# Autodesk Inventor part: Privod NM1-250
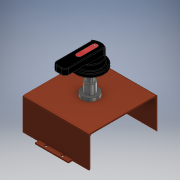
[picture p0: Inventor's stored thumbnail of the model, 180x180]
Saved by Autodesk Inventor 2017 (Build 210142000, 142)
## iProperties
Part Number: Privod NM1-250
Material: Типовые
Document SubType Name: Modeling
Designer: RSagdiev
Density: 1 g/cm^3
Appearance: По умолчанию
Author: RSagdiev
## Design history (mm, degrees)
sketch "Эскиз1"
  geometry: L1 (-26.25, 60.5)-(26.25, 60.5); L2 (26.25, 60.5)-(26.25, 52); L3 (26.25, 52)-(15.125, 52); L4 (-26.25, 52)-(-26.25, 60.5); L5 (0, 0)-(119.698, 0); L6 (0, 0)-(-104.809, 0); L7 (0, 94.88)-(0, -60.954); L8 (-15.125, 52)-(-11.125, 52); L9 (-11.125, 52)-(-11.125, 57); L10 (-13.125, 59)-(-13.125, 59); L11 (-15.125, 57)-(-15.125, 52); L12 (11.125, 52)-(11.125, 57); L13 (13.125, 59)-(13.125, 59); L14 (15.125, 52)-(11.125, 52); L15 (15.125, 57)-(15.125, 52); L16 (-15.125, 52)-(-26.25, 52); L17 (-11.125, 52)-(-15.125, 52); L18 (11.125, 52)-(-11.125, 52); L19 (15.125, 52)-(11.125, 52); A1 r 2 centre (-13.125, 57) between (-13.125, 59) and (-15.125, 57); A2 r 2 centre (-13.125, 57) between (-11.125, 57) and (-13.125, 59); A3 r 2 centre (13.125, 57) between (13.125, 59) and (11.125, 57); A4 r 2 centre (13.125, 57) between (15.125, 57) and (13.125, 59); 5 further points
  constraints: 38 end point, 10 point on line, 10 symmetric about line, 8 parallel, 8 point on circle, 4 centre point, 4 horizontal, 4 tangent, 2 perpendicular, 1 concentric, 1 midpoint, 1 vertical, 2 other
  dimensions: "d0" = 52 distance between parallel lines of L3 L6 (= 0.5 x Высота); "d1" = 8.5 distance of L1.end L2.end; "d2" = 52.5 distance between parallel lines of L2 L4 (= 0.5 x Ширина); "d3" = 4 distance of point (-15.125, 59) point (-11.125, 59); "d4" = 7 distance of point (-11.125, 59) L8.end; "d5" = 2 radius of A1 (derived); "d6" = 13.125 distance from line of L4 A1.centre (= 0.25 x d2)
extrude "Выдавливание1" new body sketch "Эскиз1" distance "d7" = 2; taper "d8" = 0 deg
mirror "Зеркальное отражение1"
sketch "Эскиз2"
  geometry: L1 (-26.25, 60.5)-(-26.25, 52) reference; L2 (26.25, 52)-(26.25, 60.5) reference; L3 (-26.25, -60.5)-(-26.25, -52) reference; L4 (26.25, -52)-(26.25, -60.5) reference; L5 (-52.5, 54)-(52.5, 54); L6 (52.5, 54)-(52.5, 52); L7 (52.5, 52)-(-52.5, 52); L8 (-52.5, 52)-(-52.5, 54); L9 (-26.25, 52)-(-15.125, 52) reference
  constraints: 8 end point, 2 parallel, 1 collinear, 1 horizontal, 1 perpendicular
  dimensions: "d13" = 105 distance of L5.start L5.end (= Ширина); "d14" = 2 distance of L5.end L6.end; "d15" = 26.25 distance between parallel lines of L1 L8 (= 0.25 x d13)
extrude "Выдавливание2" join sketch "Эскиз2" distance "d11" = 50 (computed from H1); taper "d12" = 0 deg
mirror "Зеркальное отражение2"
sketch "Эскиз3"
  geometry: L1 (-52.5, 54)-(-26.25, 54) reference; L2 (52.5, -54)-(-52.5, -54) reference; L3 (-52.5, 54)-(52.5, 54); L4 (52.5, 54)-(52.5, -54); L5 (52.5, -54)-(-52.5, -54); L6 (-52.5, -54)-(-52.5, 54); 1 further point
  constraints: 8 end point, 2 parallel, 1 horizontal, 1 perpendicular
extrude "Выдавливание3" join sketch "Эскиз3" distance "d16" = 2; taper "d17" = 0 deg
fillet "Сопряжение1" dims "d18" = 2
sketch "Эскиз4"
  geometry: L1 (52.5, -50)-(-52.5, -50) reference; L2 (52.5, -50)-(52.5, 50) reference; L3 (-52.5, 50)-(52.5, 50) reference; L4 (-52.5, 50)-(-52.5, -50) reference; L5 (-52.5, 50)-(-52.5, -50) reference; L6 (-52.5, -50)-(52.5, 50); L7 (52.5, -50)-(52.5, 50) reference; L8 (-52.5, 50)-(52.5, -50); C1 r 5 at (0, 0); 1 further point
  constraints: 4 end point, 1 centre point, 1 coincident
  dimensions: "d19" = 10 diameter of C1
extrude "Выдавливание4" cut sketch "Эскиз4" distance "d20" = 10; taper "d21" = 0 deg
sketch "Эскиз5"
  geometry: C1 r 5 at (0, 0) reference; C2 r 5 at (0, 0); C3 r 8 at (0, 0); 1 further point
  constraints: 2 centre point, 2 coincident
  dimensions: "d22" = 16 diameter of C3
extrude "Выдавливание5" new body sketch "Эскиз5" distance "d23" = 18 (= 0.333333 x H1); taper "d24" = 0 deg
sketch "Эскиз6"
  geometry: C1 r 5 at (0, 0) reference; C2 r 5 at (0, 0); 1 further point
  constraints: 1 centre point, 1 coincident
extrude "Выдавливание6" new body sketch "Эскиз6" distance "d25" = 68 (computed from H1); taper "d26" = 0 deg
sketch "Эскиз7"
  geometry: C1 r 5 at (0, 0) reference; C2 r 13 at (0, 0); C3 r 8 at (0, 0); C4 r 5 at (0, 0); 1 further point
  constraints: 3 centre point, 3 coincident
  dimensions: "d27" = 26 diameter of C2; "d28" = 16 diameter of C3; "d29" = 10 diameter of C4
extrude "Выдавливание7" new body sketch "Эскиз7" distance "d30" = 5; taper "d31" = 0 deg
extrude "Выдавливание8" join sketch "Эскиз7" distance "d32" = 20; taper "d33" = 0 deg
sketch "Эскиз8"
  geometry: C1 r 7 at (0, 0); 1 further point
  constraints: 1 centre point, 1 coincident
  dimensions: "d34" = 14 diameter of C1
extrude "Выдавливание9" new body sketch "Эскиз8" distance "d35" = 3; taper "d36" = 0 deg
fillet "Сопряжение2" dims "d37" = 3
sketch "Эскиз9"
  geometry: L1 (1, 13.17)-(-1, 13.17); L2 (-1, 13.17)-(-1, -13.17); L3 (-1, -13.17)-(1, -13.17); L4 (1, -13.17)-(1, 13.17); L5 (1, 13.17)-(-1, -13.17); L6 (-1, 13.17)-(1, -13.17); L7 (17.109, -1)-(-17.109, -1); L8 (-17.109, -1)-(-17.109, 1); L9 (-17.109, 1)-(17.109, 1); L10 (17.109, 1)-(17.109, -1); L11 (17.109, -1)-(-17.109, 1); L12 (-17.109, -1)-(17.109, 1); C1 r 4 at (0, 0) reference; C2 r 5 at (0, 0) reference; 1 further point
  constraints: 24 end point, 4 midpoint, 4 parallel, 2 horizontal, 2 perpendicular
  dimensions: "d38" = 2 distance of L3.end L2.end; "d39" = 2 distance of L7.end L8.end
extrude "Выдавливание10" cut sketch "Эскиз9" distance "d40" = 1; taper "d41" = 0 deg
sketch "Эскиз10"
  geometry: C1 r 17.5 at (0, 0); A1 r 4 centre (0, 0) between (1, -3.873) and (3.873, -1) reference; 1 further point
  constraints: 1 centre point, 1 coincident
  dimensions: "d42" = 35 diameter of C1
extrude "Выдавливание11" new body sketch "Эскиз10" distance "d43" = 6; taper "d44" = 0 deg; dims "d48" = 3, "d49" = 0
sketch "Эскиз11"
  geometry: C1 r 7 at (0, 0); C2 r 22.5 at (0, 0); 1 further point
  constraints: 2 centre point, 1 coincident
  dimensions: "d45" = 45 diameter of C2
extrude "Выдавливание12" join sketch "Эскиз11" distance "d46" = 6; taper "d47" = 0 deg
sketch "Эскиз12"
  geometry: L1 (-4, -49.361)-(4, -49.361); L2 (10, -43.361)-(10, 10.738); L3 (-10, 10.738)-(-10, -43.361); L4 (-10, -49.361)-(10, 14.361); L5 (10, -49.361)-(-10, 14.361); L6 (-12, 12.738)-(12, 12.738); A1 r 17.5 centre (0, 0) between (10, 14.361) and (0, -17.5) reference; A2 r 17.5 centre (0, 0) between (10, 14.361) and (0, -17.5) reference; A3 r 6 centre (-4, -43.361) between (-10, -43.361) and (-4, -49.361); A4 r 6 centre (4, -43.361) between (4, -49.361) and (10, -43.361); A5 r 2 centre (-12, 10.738) between (-10, 10.738) and (-12, 12.738); A6 r 2 centre (12, 10.738) between (12, 12.738) and (10, 10.738); A7 r 17.5 centre (0, 0) between (12, 12.738) and (-12, 12.738)
  constraints: 16 point on circle, 12 end point, 8 tangent, 6 point on line, 5 centre point, 2 equal radius, 2 horizontal, 2 midpoint, 1 coincident, 1 parallel, 1 perpendicular
  dimensions: "d63" = 20 distance of L4.end L5.end; "d64" = 6 radius of A3; "d66" = 10 distance from line of A1.centre L3; "d67" = 2 radius of A5; "d68" = 2 radius of A6 (derived)
extrude "Выдавливание13" join sketch "Эскиз12" distance "d55" = 10; taper "d56" = 0 deg
fillet "Сопряжение9" dims "d69" = 1
fillet "Сопряжение10" dims "d70" = 1
sketch "Эскиз13"
  geometry: L1 (0, 7.748)-(0, -17.5); L2 (-4, 7.748)-(-4, -17.5); L3 (4, -17.5)-(4, 7.748); A1 r 17.5 centre (0, 0) between (17.5, 0) and (0, -17.5) reference; A2 r 4 centre (0, 7.748) between (4, 7.748) and (-4, 7.748); A3 r 4 centre (0, -17.5) between (-4, -17.5) and (4, -17.5); 2 further points
  constraints: 8 end point, 5 point on circle, 4 tangent, 2 centre point, 1 midpoint, 1 parallel, 1 vertical
  dimensions: "d71" = 8 diameter of A3
extrude "Выдавливание14" cut sketch "Эскиз13" distance "d72" = 0.1; taper "d73" = 0 deg
sketch "Эскиз14"
  geometry: L1 (0, 9.652)-(1.649, 6.796); L2 (1.649, 6.796)-(-1.649, 6.796); L3 (-1.649, 6.796)-(0, 9.652); A1 r 4 centre (0, 7.748) between (4, 7.748) and (-4, 7.748) reference; 2 further points
  constraints: 6 end point, 1 coincident, 7 other
extrude "Выдавливание15" join sketch "Эскиз14" distance "d74" = 0.1; taper "d75" = 0 deg
node "Твердое тело1"
node "Спроецированная петля1"
node "Твердое тело2"
node "Твердое тело3"
node "Твердое тело4"
node "Твердое тело5"
node "Спроецированная петля2"
node "Твердое тело6"
node "Спроецированная петля3"
other parameters: "H1" = 54 [user parameter; used in 3 equation terms], "Высота" = 104 [user parameter; used in 1 equation term], "Ширина" = 105 [user parameter; used in 2 equation terms]
